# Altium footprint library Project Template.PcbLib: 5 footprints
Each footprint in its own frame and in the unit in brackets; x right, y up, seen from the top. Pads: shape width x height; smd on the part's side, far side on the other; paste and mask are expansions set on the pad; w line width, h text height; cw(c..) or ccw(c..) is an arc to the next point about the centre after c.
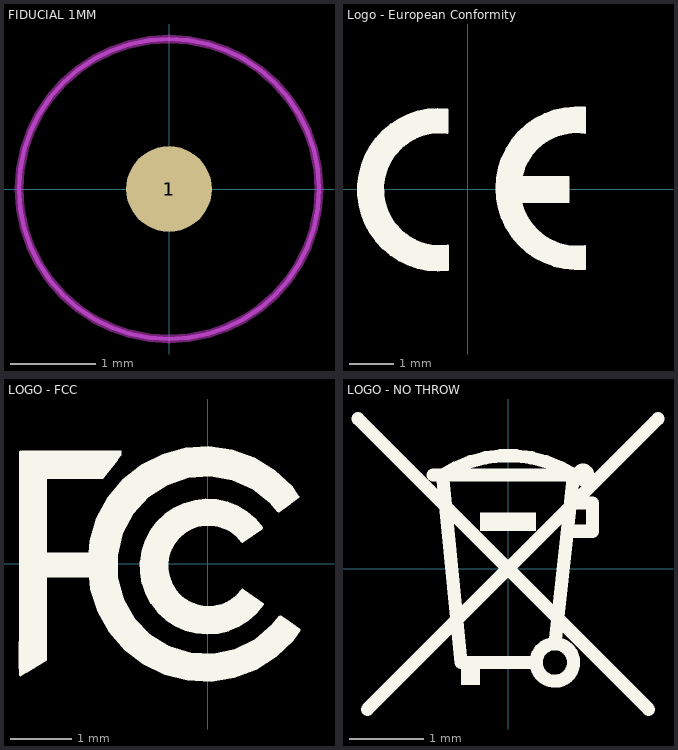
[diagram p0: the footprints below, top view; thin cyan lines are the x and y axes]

## FIDUCIAL 1MM [mm]
pads (2):
  round 0.4 smd paste-127 mask+1.3: 1(0,0)
  round 1 smd paste-1 mask+0: 1(0,0)
Top Layer keep-out:
  circle w0.1: c0,0 r1.75
M02_PCB_Notes_Fab:
  circle w0.05: c0,0 r1.75

## Logo - European Conformity [mm]
Top Overlay:
  rectangle: -0.584,1.295 -0.457,1.397
  rectangle: -0.686,-1.397 -0.457,-1.295
  rectangle: 2.464,1.295 2.667,1.473
  rectangle: 2.438,-1.422 2.667,-1.295
  region: -0.458,1.82 -0.458,1.381 -0.552,1.295 -0.596,1.299 -0.871,1.278 -1.136,1.199 -1.377,1.065 -1.585,0.884 -1.75,0.662 -1.864,0.411 -1.923,0.141 -1.922,-0.135 -1.864,-0.404 -1.749,-0.655 -1.584,-0.877 -1.376,-1.058 -1.134,-1.191 -0.87,-1.27 -0.595,-1.291 -0.584,-1.29 -0.457,-1.406 -0.456,-1.836 -0.649,-1.858 -1.035,-1.819 -1.404,-1.701 -1.741,-1.508 -2.03,-1.249 -2.259,-0.936 -2.417,-0.582 -2.498,-0.203 -2.498,0.185 -2.418,0.564 -2.26,0.918 -2.031,1.232 -1.742,1.491 -1.406,1.684 -1.037,1.802 -0.651,1.841
  region: 2.667,1.858 2.667,1.386 2.573,1.301 2.546,1.303 2.304,1.294 2.067,1.238 1.846,1.14 1.647,1.001 1.477,0.827 1.343,0.625 1.25,0.401 1.22,0.283 1.219,0.279 1.35,0.279 2.286,0.279 2.286,-0.279 1.41,-0.28 1.271,-0.281 1.214,-0.281 1.245,-0.398 1.249,-0.408 1.34,-0.621 1.475,-0.823 1.645,-0.996 1.844,-1.135 2.066,-1.234 2.302,-1.289 2.545,-1.3 2.666,-1.415 2.667,-1.803 2.476,-1.822 2.093,-1.779 1.728,-1.657 1.396,-1.463 1.112,-1.205 0.887,-0.893 0.731,-0.541 0.652,-0.165 0.652,0.22 0.731,0.596 0.887,0.948 1.112,1.26 1.397,1.518 1.729,1.712 2.094,1.834 2.476,1.877
  lines w0.006: 2.611,1.285 2.667,1.285
  lines w0.051: 1.214,-0.281 ccw(c2.48,-0.006) 2.666,-1.288 2.667,-1.803 cw(c2.491,0.027) 2.667,1.858 2.667,1.291 ccw(c2.477,0.021) 1.22,0.283 ; 1.219,-0.279 2.286,-0.279 2.286,0.279 1.219,0.279 ; -0.458,1.288 ccw(c-0.634,0.004) -0.457,-1.279 -0.456,-1.836 cw(c-0.659,-0.008) -0.458,1.82 -0.458,1.288

## LOGO - FCC [mm]
Top Overlay:
  drawing of 27 lines, arcs and shapes, not listed

## LOGO - NO THROW [mm]
Top Overlay:
  circle w0.178: c0.635,-1.27 r0.254
  circle w0.254: c1.016,1.27 r0.025
  rectangle: -0.635,-1.575 -0.381,-1.27
  rectangle: -0.381,0.508 0.381,0.762
  lines w0.178: -2.032,2.032 1.905,-1.905 ; -1.905,-1.905 2.032,2.032 ; -1.016,1.27 1.016,1.27 ; -0.889,1.27 -0.635,-1.27 0.381,-1.27 ; -0.877,1.27 cw(c0.006,-0.081) 0.889,1.27 0.635,-1.016 ; 0.889,0.508 1.143,0.508 1.143,0.635 1.143,0.889 0.889,0.889

## PCB PN (In Copper) [mm] "PCB PN (In Copper)"
Top Layer:
  text "'.PCBDocumentName'-'.BlockRev'" at -0.127,-0.275 h2.03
